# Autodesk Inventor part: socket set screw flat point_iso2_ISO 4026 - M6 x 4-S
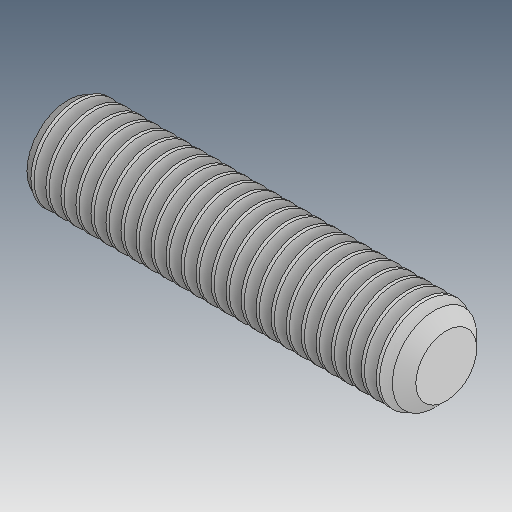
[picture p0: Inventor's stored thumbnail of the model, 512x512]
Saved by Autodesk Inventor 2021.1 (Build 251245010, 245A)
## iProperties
Created: 2019-04
Part Number: socket set screw flat point_iso2_ISO 4026 - M6 x 4-S
Material: Ogólny
Document SubType Name: Modeling
Designer: user
Density: 1 g/cm^3
Appearance: Domyślna
Author: user
Revision Number: ÈÎºÎ
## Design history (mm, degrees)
feature "ÊäÈë1"
node "Bryła1"
